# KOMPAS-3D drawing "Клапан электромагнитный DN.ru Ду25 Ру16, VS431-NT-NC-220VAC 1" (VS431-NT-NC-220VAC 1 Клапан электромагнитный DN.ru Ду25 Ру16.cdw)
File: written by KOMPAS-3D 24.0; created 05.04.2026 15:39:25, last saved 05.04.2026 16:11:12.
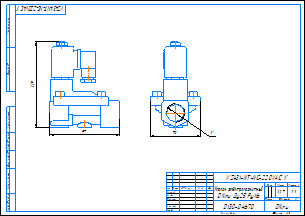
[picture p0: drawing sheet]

Document properties: c3d_UniqueCompID: ef56311e-7521-43dc-8291-0e6108b3d81d; Автор: artio; Класс точности: c; Знак неуказанной шероховатости: Шероховатость не задана; Рассекать на разрезах: Да; c3d_UniqueCompID: ef56311e-7521-43dc-8291-0e6108b3d81d; Автор: artio; Класс точности: c; Знак неуказанной шероховатости: Шероховатость не задана; Рассекать на разрезах: Да; Автор: artio; Форматы листов документа: A3; Полное имя файла: VS431-NT-NC-220VAC 1 Клапан электромагнитный DN.ru Ду25 Ру16.m3d; Масса: 1.267; Наименование: Клапан электромагнитный DN.ru Ду25 Ру16; Количество листов документа: 1; Примечание: D130-04670

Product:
- Body: Тело 1  | qty 1
    Масса: 1.729172
- Part/product: Клапан электромагнитный DN.ru Ду25 Ру16  | designation VS431-NT-NC-220VAC 1
    Масса: 1.267
    Раздел спецификации: Прочие изделия
    Примечание: D130-04670
    additional columns: ef56311e-7521-43dc-8291-0e6108b3d81d; artio; c; Шероховатость не задана; Да

Views: Вид 1, Спереди, Проекционный вид 2
Referenced files in C:\Users\artio\OneDrive\Рабочий стол\Клапан электромагнитный DN.ru\VS431\VS431-ET-NC\: VS431-ET-NC-220VAC 3-4 Клапан электромагнитный DN.ru Ду20 Ру16.m3d, VS431-ET-NC-220VAC 3-4 Клапан электромагнитный DN.ru Ду20 Ру16.cdw
Referenced files in C:\Users\artio\OneDrive\Рабочий стол\Клапан электромагнитный DN.ru\VS431\VS431-NT-NC\: VS431-NT-NC-220VAC 1 Клапан электромагнитный DN.ru Ду25 Ру16.m3d
Referenced files in C:\Users\artio\OneDrive\Рабочий стол\Клапан электромагнитный DN.ru\VS431\VS431-NT-NC\VS431-NT-NC-220VAC\Ду25\: VS431-NT-NC-220VAC 1 Клапан электромагнитный DN.ru Ду25 Ру16.m3d
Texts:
  VS431-NT-NC-220VAC 1
  Клапан электромагнитный
  DN.ru Ду25 Ру16
  VS431-NT-NC-220VAC 1"
  VS431-NT-NC-220VAC 1"-
  Клапан электромагнитный DN.ru Ду25 Ру16
  VS431-NT-NC-220VAC 1 Клапан электромагнитный DN.ru Ду25 Ру16
Dimensions and other numbers on the sheet: 0; 3; 2; 4; 70; 97; 119; 1:1; 1; 1,27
